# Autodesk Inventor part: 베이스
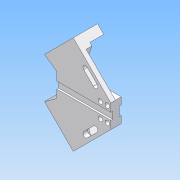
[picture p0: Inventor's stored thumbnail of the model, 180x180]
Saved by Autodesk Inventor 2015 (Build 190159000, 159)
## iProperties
Created: 2019-04
Part Number: 베이스
Material: 일반
Document SubType Name: Modeling
Designer: user
Density: 1 g/cm^3
Appearance: 기본값
Author: user
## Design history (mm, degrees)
sketch "스케치11"
  geometry: L1 (120, 20)-(20, 20); L2 (0, 20)-(0, -20); L3 (20, -20)-(120, -20); L4 (120, -20)-(120, 20); L5 (20, 20)-(20, -20); 2 further points
  constraints: 10 end point, 2 parallel, 1 coincident, 1 horizontal, 1 midpoint, 1 perpendicular, 1 vertical
  dimensions: "d31" = 20 distance from line of point (0, 0) L5; "d32" = 120 distance of L2.end L3.end; "d33" = 40 distance of L2.start L2.end; "d34" = 40 distance of L3.end L1.start; "d35" = 100 distance of L1.start L1.end
extrude "돌출3" new body sketch "스케치11" distance "d36" = 18; taper "d37" = 0 deg
sketch "스케치12"
  geometry: L1 (-20, -20)-(-20, 20) reference; L2 (-120, 20)-(-120, -20) reference; L3 (-20, -20)-(-84.853, -84.853); L4 (-84.853, -84.853)-(-169.706, 0); L5 (-120, 0)-(-169.706, 0); L6 (-20, 0)-(-20, -20); L7 (-20, 0)-(-120, 0); 1 further point
  constraints: 10 end point, 2 horizontal, 2 midpoint, 1 collinear, 1 horizontal alignment, 1 point on line
  dimensions: "d38" = 120 distance of point (0, 0) L3.end; "d39" = 120 distance of L3.end L4.end; "d40" = 90 deg angle of L3 L4
extrude "돌출4" join sketch "스케치12" distance "d41" = 18; taper "d42" = 0 deg
sketch "스케치13"
  geometry: L1 (-20, -20)-(-20, 20) reference; L2 (-169.706, 0)-(-84.853, 84.853) reference; L3 (-134.35, -35.355)-(-113, -20); L4 (-113, -20)-(-113, 20); L5 (0, 0)-(-169.706, 0); L6 (-84.853, -84.853)-(-169.706, 0) reference; L7 (-20, 0)-(-169.706, 0); L8 (-169.706, 0)-(-134.35, -35.355); L9 (-169.706, 0)-(-134.35, 35.355); L10 (-113, 20)-(-134.35, 35.355); 1 further point
  constraints: 14 end point, 3 point on line, 2 midpoint, 1 horizontal, 1 horizontal alignment, 1 vertical
  dimensions: "d45" = 40 distance of L3.end L4.end; "d50" = 93 distance of L7.start point (-113, 0); "d54" = 50 distance of L5.end L3.start; "d55" = 50 distance of L5.end L9.end
extrude "돌출5" cut sketch "스케치13" distance "d56" = 18; taper "d57" = 0 deg
sketch "스케치14"
  geometry: L1 (-113, -20)-(-134.35, -35.355) reference; L2 (-134.35, -35.355)-(-84.853, -84.853) reference; L3 (-84.853, -84.853)-(-20, -20) reference; L4 (-122.011, -26.481)-(-74.246, -74.246); L5 (-122.011, -26.481)-(-134.35, -35.355); L6 (-74.246, -74.246)-(-84.853, -84.853); L7 (-134.35, -35.355)-(-84.853, -84.853); 1 further point
  constraints: 8 end point, 2 point on line, 1 collinear, 1 parallel
  dimensions: "d58" = 15 distance between parallel lines of L2 L4
extrude "돌출6" join sketch "스케치14" distance "d59" = 24; taper "d60" = 0 deg
sketch "스케치15"
  geometry: L1 (0, 0)-(40, 0) reference; L2 (14, 3)-(26, 3); L3 (26, 3)-(26, 0); L4 (26, 0)-(14, 0); L5 (14, 0)-(14, 3); 2 further points
  constraints: 8 end point, 2 midpoint, 2 parallel, 1 horizontal, 1 perpendicular
  dimensions: "d61" = 3 distance of L2.end L3.end; "d62" = 12 distance of L2.start L2.end
extrude "돌출7" cut sketch "스케치15" stored distance "d63" = 24; taper "d64" = 0 deg
sketch "스케치16"
  geometry: L1 (0, 18)-(40, 18) reference; L2 (12, 18)-(28, 18); L3 (28, 18)-(28, 14.5); L4 (28, 14.5)-(12, 14.5); L5 (12, 14.5)-(12, 18); 2 further points
  constraints: 8 end point, 2 parallel, 1 collinear, 1 horizontal, 1 midpoint, 1 perpendicular, 1 vertical alignment
  dimensions: "d65" = 3.5 distance between parallel lines of L1 L4; "d66" = 16 distance between parallel lines of L3 L5
extrude "돌출8" cut sketch "스케치16" stored distance "d67" = 24; taper "d68" = 0 deg
sketch "스케치17"
  geometry: L1 (-74.246, -74.246)-(-20, -20) reference; L2 (-70.711, -70.711)-(-77.782, -49.497); L3 (-77.782, -49.497)-(-48.284, -20); L4 (-48.284, -20)-(-20, -20); L5 (-134.35, -35.355)-(-84.853, -84.853) reference; L6 (-70.711, -70.711)-(-20, -20); 1 further point
  constraints: 8 end point, 1 horizontal, 1 parallel, 1 point on line
  dimensions: "d70" = 20 distance from line of L2.start L5; "d71" = 30 distance from line of L5 L2.end; "d72" = 20 distance between parallel lines of L3 L1
extrude "돌출9" cut sketch "스케치17" distance "d73" = 10; taper "d74" = 0 deg
sketch "스케치18"
  geometry: L1 (-20, -20)-(-70.711, -70.711) reference; L2 (-63.64, -49.497)-(-46.669, -32.527); L3 (-43.375, -35.593)-(-60.457, -52.679); L4 (-50.167, -29.696)-(-66.818, -46.312); L5 (-134.35, -35.355)-(-84.853, -84.853) reference; L6 (-63.64, -49.497)-(-46.669, -32.527); A1 r 4.5 centre (-63.64, -49.497) between (-66.818, -46.312) and (-60.457, -52.679); A2 r 4.5 centre (-46.669, -32.527) between (-43.602, -35.82) and (-50.167, -29.696); 1 further point
  constraints: 9 end point, 5 point on circle, 2 centre point, 2 coincident, 2 point on line, 2 tangent, 1 parallel
  dimensions: "d75" = 10 distance between parallel lines of L1 L2; "d76" = 9 diameter of A1; "d77" = 9 diameter of A2; "d78" = 40 distance from line of L5 L2.start; "d79" = 24 distance of L6.start L2.end; "d80" = 17.0822 horizontal distance of L3.start L3.end; "d81" = 16.61654 vertical distance of L4.start L4.end
extrude "돌출10" cut sketch "스케치18" stored distance "d82" = 10; taper "d83" = 0 deg
sketch "스케치20"
  geometry: L1 (-20, 20)-(-20, 6) reference; 3 further points
  dimensions: "d84" = 12 distance of point (-26, 13) point (-38, 13); "d85" = 6 distance from line of L1 point (-26, 13)
hole "구멍1" sketch "스케치20" at (-26, 13), (-38, 13) diameter "d86" = 4.5; stored, may be unused: countersink angle "d90" = 90 deg, drill point angle "d92" = 118 deg; dims "d87" = 6, "d88" = 8, "d89" = 8, "d91" = 18
sketch "스케치21"
  geometry: L1 (-134.35, -35.355)-(-84.853, -84.853) reference; L2 (-122.011, -26.481)-(-134.35, -35.355) reference; 2 further points
  constraints: 1 other
  dimensions: "d93" = 35 distance from line of L2 point (-103.104, -55.995); "d94" = 7.5 distance from line of L1 point (-103.104, -55.995)
feature "엠보싱1" sketch "스케치21" dims "d31" = 20, "d32" = 120, "d33" = 40, "d34" = 40, "d35" = 100, "d95" = 0.5, "d96" = 0
fillet "모깎기1" dims "d97" = 3
fillet "모깎기2" dims "d98" = 3
fillet "모깎기3" dims "d99" = 3
node "솔리드3"
mirror "대칭1"
mirror "대칭2"
mirror "대칭3"
mirror "대칭4"
mirror "대칭5"
